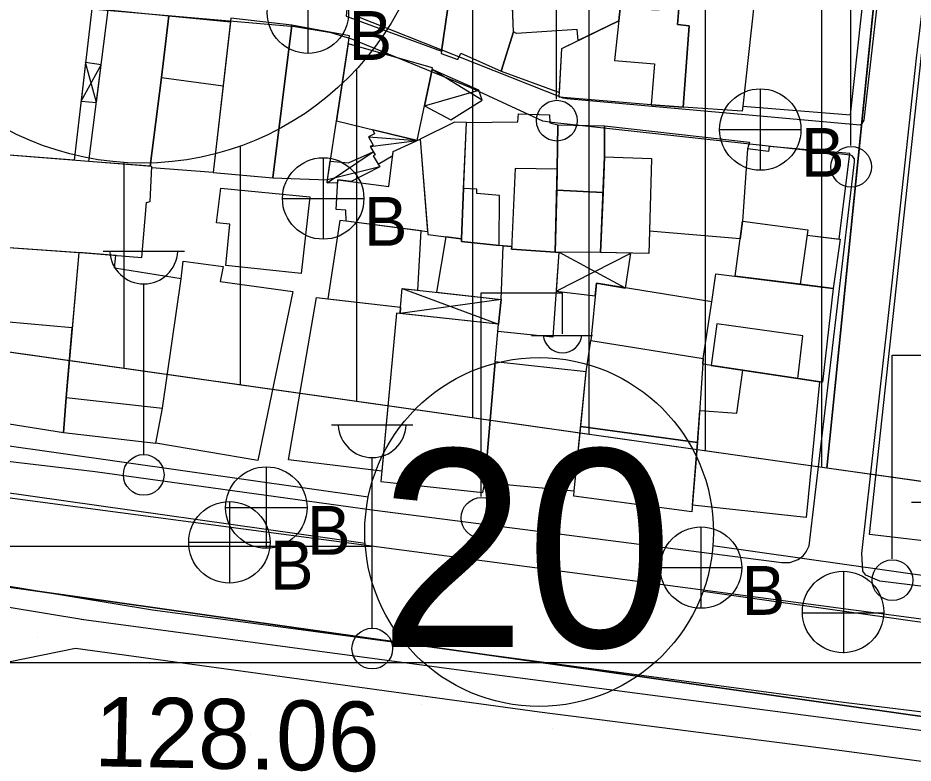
# Model space of a CAD drawing. Extents: x 417997 to 421451, y 4451742 to 4455216.
# Drawn here: x 419493.1 to 419570.1, y 4452369.2 to 4452433.3 of the extents above; entities that cross this region are included whole.
import ezdxf

# ---------------------------------------------------------------- set-up
doc = ezdxf.new("R2010")
doc.units = 0
for name, color, linetype in [('ADA', 7, 'Continuous'), ('ADAKENARI', 7, 'Continuous'), ('B_Mesken', 7, 'Continuous'), ('B_Sundurma', 7, 'Continuous'), ('B_Teras', 7, 'Continuous'), ('Default', 7, 'Continuous'), ('KALDIRIM', 7, 'Continuous'), ('KD_DAIRE', 7, 'Continuous'), ('KD_YGEN', 7, 'Continuous'), ('PL_AYA_REKREASYON_AL', 7, 'Continuous'), ('PL_KON_MEV_350', 7, 'Continuous'), ('PL_SAY_ORTAOGRETIM', 7, 'Continuous'), ('S_Cad_Sok_Lambasi', 7, 'Continuous'), ('S_Elektrik_Diregi', 7, 'Continuous'), ('S_Rogar_Kapagi', 7, 'Continuous'), ('S_Rogar_Kapagi_Buski', 7, 'Continuous'), ('Sinir_Duvar_tek_tarafa_ait', 7, 'Continuous'), ('SIT_TR_KULTUR', 7, 'Continuous'), ('SM_DAIRE', 7, 'Continuous'), ('SN_KULTUR_REKREASYON', 7, 'Continuous'), ('TR_ORTAYOGUNKONUT', 7, 'Continuous'), ('TR_PARKALANI', 7, 'Continuous'), ('Y_Kot_Noktasi', 7, 'Continuous'), ('Yol_Kaldirim_kenari_bordurtasi', 7, 'Continuous'), ('Yol_Sose', 7, 'Continuous')]:
    doc.layers.add(name, color=color, linetype=linetype)

# ---------------------------------------------------------------- blocks, each defined once
blk = doc.blocks.new('POINT_DISPLAY')
at = {"layer": 'Default'}
blk.add_line((0, 0), (0, 0), dxfattribs=at)

msp = doc.modelspace()

# ---------------------------------------------------------------- linework, layer by layer
at = {"layer": 'ADA'}
msp.add_line((419567.658, 4452443.954), (419562.661, 4452394.609), dxfattribs=at)
msp.add_line((419567.658, 4452443.954), (419562.661, 4452394.609), dxfattribs=at)
at = {"layer": 'ADAKENARI'}
for p, q in [((419562.661, 4452394.609), (419462.91, 4452408.734)), ((419562.661, 4452394.609), (419462.91, 4452408.734)), ((419687.358, 4452376.952), (419562.661, 4452394.609)), ((419687.358, 4452376.952), (419562.661, 4452394.609)), ((419457, 4452389.371), (419746.184, 4452348.423)), ((419457, 4452389.371), (419746.184, 4452348.423))]:
    msp.add_line(p, q, dxfattribs=at)
at = {"layer": 'B_Mesken'}
for points in [[(419534.636, 4452428.737), (419535.697, 4452432.128), (419535.439, 4452438.84), (419529.54, 4452438.143), (419530.016, 4452433.988), (419529.484, 4452430.246), (419530.911, 4452429.721), (419531.173, 4452430.279)], [(419535.451, 4452438.544), (419544.263, 4452439.061), (419544.501, 4452438.07), (419545.148, 4452434.142), (419544.882, 4452434.154), (419544.761, 4452433.049), (419541.274, 4452431.357), (419541.187, 4452432.317), (419535.955, 4452431.977), (419535.697, 4452432.128)], [(419529.578, 4452437.816), (419521.616, 4452437.017), (419521.304, 4452433.452), (419529.513, 4452430.454), (419530.016, 4452433.988)], [(419545.148, 4452434.142), (419544.501, 4452438.07), (419550.848, 4452437.805), (419550.868, 4452434.889), (419556.398, 4452434.611), (419555.425, 4452425.719), (419555.383, 4452425.28), (419550.308, 4452425.64), (419550.829, 4452432.619), (419549.824, 4452432.742), (419549.929, 4452434.129), (419548.261, 4452434.335), (419548.24, 4452434.006)], [(419556.657, 4452436.972), (419555.425, 4452425.719), (419564.699, 4452424.987), (419565.931, 4452436.2)], [(419490.461, 4452421.659), (419492.124, 4452434.775), (419499.427, 4452434.098), (419497.91, 4452421.073)], [(419499.179, 4452420.974), (419500.841, 4452433.998), (419506.07, 4452433.478), (419505.424, 4452428.194), (419504.46, 4452420.558)], [(419547.542, 4452425.83), (419539.643, 4452426.509), (419539.857, 4452430.67), (419544.761, 4452433.049), (419544.882, 4452434.154), (419548.24, 4452434.006), (419548.261, 4452434.335), (419549.929, 4452434.129), (419549.824, 4452432.742), (419550.829, 4452432.619), (419550.308, 4452425.64)], [(419509.876, 4452420.017), (419504.585, 4452420.427), (419504.591, 4452420.548), (419504.46, 4452420.558), (419505.424, 4452428.194), (419506.07, 4452433.478), (419511.362, 4452432.983)], [(419511.397, 4452433.288), (419509.876, 4452420.017), (419515.002, 4452419.559), (419516.642, 4452432.69)], [(419515.002, 4452419.559), (419519.695, 4452419.381), (419521.594, 4452431.767), (419516.642, 4452432.69)], [(419534.636, 4452428.737), (419539.663, 4452426.892), (419539.857, 4452430.67), (419541.274, 4452431.357), (419541.187, 4452432.317), (419535.955, 4452431.977), (419535.697, 4452432.128)], [(419520.472, 4452424.448), (419527.416, 4452422.772), (419528.727, 4452429.022), (419521.49, 4452431.088)], [(419539.289, 4452413.177), (419535.538, 4452413.441), (419535.548, 4452413.654), (419534.808, 4452413.72), (419534.473, 4452413.757), (419531.22, 4452414.089), (419531.231, 4452414.328), (419531.413, 4452418.641), (419531.653, 4452424.333), (419536.08, 4452424.366), (419536.122, 4452425.075), (419538.81, 4452424.974), (419538.818, 4452424.295), (419539.515, 4452424.119), (419539.463, 4452420.296), (419539.419, 4452418.514)], [(419527.688, 4452422.884), (419528.329, 4452414.678), (419531.231, 4452414.328), (419531.653, 4452424.333), (419530.626, 4452424.357)], [(419539.515, 4452424.119), (419543.54, 4452424.036), (419543.541, 4452421.375), (419543.411, 4452418.289), (419539.419, 4452418.514), (419539.463, 4452420.296)], [(419543.541, 4452421.375), (419543.54, 4452424.036), (419556.008, 4452422.623), (419555.846, 4452422.045), (419555.407, 4452415.829), (419555.206, 4452414.309), (419547.403, 4452414.966), (419547.357, 4452413.06), (419543.194, 4452413.137), (419543.411, 4452418.289)], [(419528.309, 4452414.932), (419521.323, 4452415.827), (419521.276, 4452416.775), (419520.438, 4452416.849), (419520.596, 4452419.392), (419524.977, 4452418.806), (419525.357, 4452421.817), (419527.688, 4452422.884)], [(419503.729, 4452412.715), (419504.142, 4452417.447), (419504.441, 4452417.525), (419504.591, 4452420.548), (419490.461, 4452421.659), (419489.818, 4452413.745), (419498.457, 4452413.143)], [(419563.709, 4452414.299), (419564.624, 4452421.643), (419557.702, 4452422.26), (419557.64, 4452421.821), (419555.846, 4452422.045), (419555.407, 4452415.829), (419561.03, 4452415.08), (419560.966, 4452414.619)], [(419510.149, 4452415.697), (419510.518, 4452418.668), (419518.192, 4452417.939), (419517.451, 4452411.339), (419510.947, 4452412.012), (419511.318, 4452415.582)], [(419539.419, 4452418.514), (419543.411, 4452418.289), (419543.194, 4452413.137), (419539.289, 4452413.177)], [(419527.461, 4452409.902), (419527.764, 4452415.002), (419521.323, 4452415.827), (419520.774, 4452415.89), (419519.729, 4452409.166), (419525.976, 4452408.435), (419526.131, 4452410.051)], [(419560.966, 4452414.619), (419563.801, 4452414.288), (419563.193, 4452410.052), (419560.376, 4452410.406), (419554.783, 4452411.108), (419555.407, 4452415.829), (419561.03, 4452415.08)], [(419497.739, 4452406.664), (419488.104, 4452407.54), (419488.629, 4452414.021), (419489.834, 4452413.945), (419489.818, 4452413.745), (419498.309, 4452413.154)], [(419529.889, 4452414.49), (419529.07, 4452409.722), (419534.633, 4452409.099), (419534.808, 4452413.72), (419534.473, 4452413.757), (419531.22, 4452414.089), (419531.231, 4452414.328)], [(419504.93, 4452396.763), (419505.523, 4452399.767), (419507.121, 4452410.889), (419501.385, 4452411.796), (419501.503, 4452412.896), (419498.309, 4452413.154), (419497.214, 4452400.67), (419496.996, 4452397.681)], [(419539.604, 4452413.173), (419539.1, 4452405.875), (419534.349, 4452406.339), (419534.402, 4452406.969), (419534.633, 4452409.099), (419534.808, 4452413.72), (419535.548, 4452413.654), (419535.538, 4452413.441), (419539.289, 4452413.177)], [(419507.121, 4452410.889), (419507.284, 4452412.398), (419510.726, 4452411.933), (419510.461, 4452410.639), (419516.736, 4452409.801), (419513.715, 4452395.248), (419504.93, 4452396.763), (419505.523, 4452399.767)], [(419552.772, 4452408.888), (419553.119, 4452411.317), (419563.193, 4452410.052), (419562.289, 4452401.998), (419551.989, 4452403.536), (419552.022, 4452404.036)], [(419542.349, 4452405.581), (419552.022, 4452404.036), (419552.772, 4452408.888), (419542.842, 4452410.493)], [(419524.378, 4452394.348), (419516.363, 4452395.315), (419518.757, 4452409.279), (419525.976, 4452408.435), (419525.954, 4452407.902), (419525.636, 4452407.938)], [(419534.133, 4452403.751), (419534.402, 4452406.969), (419525.636, 4452407.938), (419524.295, 4452393.459), (419533.061, 4452392.501), (419533.245, 4452393.372)], [(419488.104, 4452407.54), (419487.461, 4452399.181), (419496.996, 4452397.681), (419497.214, 4452400.67), (419497.739, 4452406.664)], [(419552.022, 4452404.036), (419551.534, 4452396.822), (419541.484, 4452398.19), (419541.964, 4452402.888), (419542.349, 4452405.581)], [(419534.133, 4452403.751), (419533.245, 4452393.372), (419540.918, 4452392.648), (419541.964, 4452402.888)], [(419562.039, 4452402.036), (419560.872, 4452390.374), (419551.104, 4452391.419), (419551.534, 4452396.822), (419551.719, 4452399.55), (419554.915, 4452399.338), (419555.431, 4452403.022), (419560.171, 4452402.314)], [(419541.484, 4452398.19), (419551.534, 4452396.822), (419551.058, 4452390.84), (419540.889, 4452392.208), (419540.918, 4452392.648)]]:
    msp.add_lwpolyline(points, close=True, dxfattribs=at)
at = {"layer": 'B_Sundurma'}
for p, q in [((419498.502, 4452426.155), (419500.238, 4452429.268)), ((419499.825, 4452426.035), (419498.89, 4452429.484)), ((419533.008, 4452426.237), (419528.696, 4452428.872)), ((419528.04, 4452425.746), (419532.711, 4452427.108)), ((419523.221, 4452423.076), (419527.417, 4452422.76)), ((419523.388, 4452422.246), (419527.416, 4452422.772)), ((419519.677, 4452419.141), (419523.646, 4452421.807)), ((419524.202, 4452420.494), (419519.695, 4452419.381)), ((419539.371, 4452409.81), (419545.802, 4452413.089)), ((419545.348, 4452410.088), (419539.604, 4452413.173)), ((419526.131, 4452410.051), (419534.402, 4452406.969)), ((419534.633, 4452409.099), (419525.954, 4452407.902))]:
    msp.add_line(p, q, dxfattribs=at)
for points in [[(419498.502, 4452426.155), (419499.825, 4452426.035), (419500.238, 4452429.268), (419498.89, 4452429.484)], [(419528.04, 4452425.746), (419530.319, 4452424.546), (419533.008, 4452426.237), (419532.711, 4452427.108), (419528.696, 4452428.872)], [(419523.593, 4452423.695), (419523.752, 4452423.354), (419523.221, 4452423.076), (419523.628, 4452422.375), (419523.388, 4452422.246), (419523.806, 4452421.535), (419523.635, 4452421.456), (419524.063, 4452420.744), (419525.316, 4452421.491), (419525.357, 4452421.817), (419527.417, 4452422.76), (419527.416, 4452422.772)], [(419524.063, 4452420.744), (419524.202, 4452420.494), (419521.73, 4452419.24), (419520.596, 4452419.392), (419520.578, 4452419.108), (419519.677, 4452419.141), (419519.695, 4452419.381), (419519.942, 4452420.993), (419521.514, 4452420.857), (419523.646, 4452421.807), (419523.806, 4452421.535), (419523.635, 4452421.456)], [(419539.371, 4452409.81), (419542.734, 4452409.42), (419542.842, 4452410.493), (419545.348, 4452410.088), (419545.802, 4452413.089), (419543.194, 4452413.137), (419539.604, 4452413.173)], [(419525.976, 4452408.435), (419526.131, 4452410.051), (419534.633, 4452409.099), (419534.402, 4452406.969), (419525.954, 4452407.902)]]:
    msp.add_lwpolyline(points, close=True, dxfattribs=at)
at = {"layer": 'B_Teras'}
for points in [[(419544.882, 4452434.154), (419544.389, 4452429.661), (419547.832, 4452429.369), (419547.542, 4452425.83), (419550.308, 4452425.64), (419550.829, 4452432.619), (419549.824, 4452432.742), (419549.929, 4452434.129), (419548.261, 4452434.335), (419548.24, 4452434.006)], [(419509.876, 4452420.017), (419504.585, 4452420.427), (419504.591, 4452420.548), (419504.46, 4452420.558), (419505.424, 4452428.194), (419510.732, 4452427.483)], [(419547.404, 4452415.005), (419547.357, 4452413.06), (419543.194, 4452413.137), (419543.541, 4452421.375), (419547.58, 4452421.214)], [(419535.86, 4452420.35), (419535.538, 4452413.441), (419539.289, 4452413.177), (419539.463, 4452420.296)], [(419531.231, 4452414.328), (419531.22, 4452414.089), (419534.473, 4452413.757), (419534.487, 4452418.055), (419532.551, 4452418.222), (419532.562, 4452418.581), (419531.413, 4452418.641)], [(419554.783, 4452411.108), (419555.407, 4452415.829), (419561.03, 4452415.08), (419560.376, 4452410.406)], [(419498.309, 4452413.154), (419497.214, 4452400.67), (419505.523, 4452399.767), (419507.121, 4452410.889), (419501.385, 4452411.796), (419501.503, 4452412.896)], [(419560.171, 4452402.314), (419560.592, 4452405.973), (419553.208, 4452407.007), (419552.7, 4452403.43)]]:
    msp.add_lwpolyline(points, close=True, dxfattribs=at)
at = {"layer": 'KALDIRIM'}
for p, q in [((419523.215, 4452392.115), (419460.546, 4452400.988)), ((419523.215, 4452392.115), (419460.546, 4452400.988)), ((419522.944, 4452388.113), (419459.364, 4452397.116)), ((419522.944, 4452388.113), (419459.364, 4452397.116)), ((419747.671, 4452360.332), (419552.863, 4452387.917)), ((419747.671, 4452360.332), (419552.863, 4452387.917)), ((419747.175, 4452356.362), (419552.012, 4452383.997)), ((419747.175, 4452356.362), (419552.012, 4452383.997))]:
    msp.add_line(p, q, dxfattribs=at)
at = {"layer": 'KD_DAIRE'}
msp.add_circle((419537.911, 4452389.112), 15, dxfattribs=at)
msp.add_circle((419537.911, 4452389.112), 15, dxfattribs=at)
at = {"layer": 'PL_AYA_REKREASYON_AL'}
msp.add_line((419746.184, 4452348.423), (419457, 4452389.371), dxfattribs=at)
msp.add_line((419746.184, 4452348.423), (419457, 4452389.371), dxfattribs=at)
at = {"layer": 'PL_KON_MEV_350'}
msp.add_lwpolyline([(419567.658, 4452443.954), (419562.661, 4452394.609), (419462.91, 4452408.734), (419316.34, 4452479.861)], dxfattribs=at)
at = {"layer": 'PL_SAY_ORTAOGRETIM'}
msp.add_lwpolyline([(419659.386, 4452433.765), (419690.951, 4452406.625), (419690.066, 4452398.955), (419687.358, 4452376.952), (419562.661, 4452394.609), (419567.658, 4452443.954), (419624.577, 4452438.19)], close=True, dxfattribs=at)
msp.add_lwpolyline([(419659.386, 4452433.765), (419690.951, 4452406.625), (419690.066, 4452398.955), (419687.358, 4452376.952), (419562.661, 4452394.609), (419567.658, 4452443.954), (419624.577, 4452438.19)], close=True, dxfattribs=at)
at = {"layer": 'S_Cad_Sok_Lambasi'}
for p, q in [((419500.397, 4452413.271), (419507.397, 4452413.271)), ((419503.897, 4452395.771), (419503.897, 4452410.446)), ((419520.056, 4452398.34), (419527.056, 4452398.34)), ((419523.556, 4452380.84), (419523.556, 4452395.515)), ((419569.952, 4452391.671), (419576.952, 4452391.671))]:
    msp.add_line(p, q, dxfattribs=at)
for centre in [(419503.897, 4452394.021), (419523.556, 4452379.09)]:
    msp.add_circle(centre, 1.75, dxfattribs=at)
for centre in [(419503.897, 4452413.375), (419523.556, 4452398.444)]:
    msp.add_arc(centre, 2.929, 183.298, 356.90719, dxfattribs=at)
at = {"layer": 'S_Elektrik_Diregi'}
for p, q in [((419539.398, 4452426.313), (419539.398, 4452443.813)), ((419564.718, 4452422.341), (419564.718, 4452439.841)), ((419532.917, 4452392.161), (419532.917, 4452409.661)), ((419532.917, 4452409.661), (419539.917, 4452409.661)), ((419539.917, 4452406.161), (419539.917, 4452409.661)), ((419537.257, 4452406.021), (419542.507, 4452406.021)), ((419568.263, 4452386.809), (419568.263, 4452404.309)), ((419568.263, 4452404.309), (419575.263, 4452404.309))]:
    msp.add_line(p, q, dxfattribs=at)
for centre in [(419539.434, 4452424.478), (419564.754, 4452420.506), (419532.953, 4452390.326), (419568.299, 4452384.973)]:
    msp.add_circle(centre, 1.75, dxfattribs=at)
msp.add_arc((419539.918, 4452406.174), 1.658, 184.83843, 355.14641, dxfattribs=at)
at = {"layer": 'S_Rogar_Kapagi'}
for p, q in [((419564.109, 4452378.709), (419564.109, 4452385.709)), ((419560.539, 4452382.174), (419567.539, 4452382.174))]:
    msp.add_line(p, q, dxfattribs=at)
msp.add_circle((419564.056, 4452382.238), 3.5, dxfattribs=at)
at = {"layer": 'S_Rogar_Kapagi_Buski'}
for p, q in [((419518.023, 4452437.265), (419518.023, 4452430.265)), ((419556.933, 4452427.215), (419556.933, 4452420.215)), ((419553.433, 4452423.715), (419560.433, 4452423.715)), ((419519.333, 4452421.286), (419519.333, 4452414.286)), ((419515.833, 4452417.786), (419522.833, 4452417.786)), ((419514.443, 4452394.716), (419514.443, 4452387.716)), ((419511.263, 4452391.726), (419511.263, 4452384.726)), ((419510.943, 4452391.216), (419517.943, 4452391.216)), ((419551.833, 4452389.556), (419551.833, 4452382.556)), ((419507.763, 4452388.226), (419514.763, 4452388.226)), ((419548.333, 4452386.056), (419555.333, 4452386.056))]:
    msp.add_line(p, q, dxfattribs=at)
for centre in [(419518.023, 4452433.765), (419556.933, 4452423.715), (419519.333, 4452417.786), (419514.443, 4452391.216), (419511.263, 4452388.226), (419551.833, 4452386.056)]:
    msp.add_circle(centre, 3.5, dxfattribs=at)
at = {"layer": 'Sinir_Duvar_tek_tarafa_ait'}
for points in [[(419611.72, 4452383.569), (419566.314, 4452388.908), (419572.274, 4452443.575), (419618.995, 4452438.277), (419660.716, 4452432.816), (419680.746, 4452415.705)], [(419448.361, 4452374.806), (419449.762, 4452375.579), (419450.624, 4452376.075), (419452.667, 4452377.445), (419468.665, 4452373.244), (419486.608, 4452376.806), (419498.029, 4452379.117), (419516.631, 4452376.563), (419537.931, 4452373.659), (419563.527, 4452370.397), (419589.022, 4452366.976), (419618.734, 4452363.038), (419642.331, 4452359.964), (419680.1, 4452354.952)]]:
    msp.add_lwpolyline(points, dxfattribs=at)
at = {"layer": 'SIT_TR_KULTUR'}
for p, q in [((419110.241, 4452387.891), (419523.484, 4452387.891)), ((419110.241, 4452387.891), (419523.484, 4452387.891)), ((419110.134, 4452377.891), (419599.001, 4452377.891)), ((419110.134, 4452377.891), (419599.001, 4452377.891))]:
    msp.add_line(p, q, dxfattribs=at)
at = {"layer": 'SM_DAIRE'}
msp.add_circle((419503.798, 4452445.833), 25, dxfattribs=at)
msp.add_circle((419503.798, 4452445.833), 25, dxfattribs=at)
at = {"layer": 'SN_KULTUR_REKREASYON'}
msp.add_line((419780.252, 4452353.89), (419451.753, 4452397.389), dxfattribs=at)
msp.add_line((419780.252, 4452353.89), (419451.753, 4452397.389), dxfattribs=at)
at = {"layer": 'TR_ORTAYOGUNKONUT'}
for p, q in [((419532.22, 4452398.919), (419532.22, 4452496.464)), ((419532.22, 4452398.919), (419532.22, 4452496.464)), ((419542.22, 4452397.503), (419542.22, 4452495.483)), ((419542.22, 4452397.503), (419542.22, 4452495.483)), ((419552.22, 4452396.087), (419552.22, 4452494.502)), ((419552.22, 4452396.087), (419552.22, 4452494.502)), ((419562.22, 4452394.671), (419562.22, 4452493.521)), ((419562.22, 4452394.671), (419562.22, 4452493.521)), ((419522.22, 4452400.335), (419522.22, 4452428.933)), ((419522.22, 4452400.335), (419522.22, 4452428.933)), ((419512.22, 4452401.751), (419512.22, 4452422.295)), ((419512.22, 4452401.751), (419512.22, 4452422.295)), ((419502.22, 4452403.167), (419502.22, 4452420.883)), ((419502.22, 4452403.167), (419502.22, 4452420.883))]:
    msp.add_line(p, q, dxfattribs=at)
at = {"layer": 'Yol_Kaldirim_kenari_bordurtasi'}
for points in [[(419444.875, 4452392.746), (419451.159, 4452390.757), (419469.008, 4452386.571), (419482.224, 4452384.314), (419498.752, 4452381.588)], [(419498.519, 4452381.62), (419531.652, 4452377.182), (419578.39, 4452371.068)]]:
    msp.add_lwpolyline(points, dxfattribs=at)
at = {"layer": 'Yol_Sose'}
for points in [[(419570.776, 4452467.72), (419565.837, 4452424.522), (419565.655, 4452424.222), (419565.514, 4452424.102), (419540.291, 4452426.344), (419539.99, 4452426.405), (419522.024, 4452433.508)], [(419680.254, 4452369.398), (419650.127, 4452373.883), (419602.133, 4452380.618), (419567.203, 4452384.9), (419566.023, 4452385.405), (419565.744, 4452385.746), (419565.669, 4452387.267), (419568.27, 4452410.533), (419570.379, 4452429.848), (419572.028, 4452443.659), (419572.15, 4452443.919), (419572.431, 4452444.198), (419572.832, 4452444.236), (419614.267, 4452439.286), (419634.483, 4452436.623), (419660.83, 4452433.255), (419661.551, 4452432.932), (419661.911, 4452432.71), (419680.756, 4452416.668)], [(419489.249, 4452395.561), (419499.73, 4452394.301), (419523.536, 4452391.005), (419558.786, 4452386.503), (419559.466, 4452386.501), (419560.188, 4452386.738), (419560.609, 4452387.056), (419560.89, 4452387.395), (419561.132, 4452387.914), (419565.045, 4452420.937), (419565.025, 4452421.197), (419564.846, 4452421.458), (419564.706, 4452421.499), (419538.998, 4452424.322), (419538.237, 4452424.445), (419532.043, 4452427.31), (419521.789, 4452431.471), (419520.03, 4452432.018), (419516.889, 4452432.531), (419500.023, 4452434.018)], [(419473.745, 4452376.738), (419491.54, 4452379.376), (419470.933, 4452382.923), (419447.673, 4452388.602), (419442.552, 4452390.061), (419442.297, 4452390.626), (419442.329, 4452390.892), (419445.929, 4452393.514), (419447.17, 4452394.209), (419448.684, 4452393.886), (419464.599, 4452389.151), (419479.539, 4452386.407), (419491.27, 4452384.632), (419504.647, 4452382.425), (419516.545, 4452380.851)], [(419516.545, 4452380.851), (419534.037, 4452378.503), (419564.096, 4452374.479), (419573.722, 4452373.299), (419574.702, 4452372.935), (419580.638, 4452369.929), (419581.479, 4452369.826), (419610.918, 4452365.884), (419618.03, 4452367.317), (419619.312, 4452367.372), (419658.957, 4452362.048), (419680.144, 4452359.116)]]:
    msp.add_lwpolyline(points, dxfattribs=at)

# ---------------------------------------------------------------- block references
at = {"layer": 'TR_PARKALANI', "xscale": 0.1, "yscale": 0.10000000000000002}
for p in [(419494.775, 4452380.026), (419494.775, 4452380.026), (419506.38, 4452380.68), (419506.38, 4452380.68), (419504.419, 4452377.773), (419504.419, 4452377.773), (419542.585, 4452376.91), (419542.585, 4452376.91), (419524.319, 4452374.817), (419524.319, 4452374.817), (419527.813, 4452374.305), (419527.813, 4452374.305), (419554.732, 4452374.531), (419554.732, 4452374.531), (419513.041, 4452371.7), (419513.041, 4452371.7), (419539.092, 4452372.212), (419539.092, 4452372.212), (419564.017, 4452370.534), (419564.017, 4452370.534)]:
    msp.add_blockref('POINT_DISPLAY', p, dxfattribs=at)

# ---------------------------------------------------------------- texts
at = {"layer": 'KD_YGEN'}
msp.add_text('20', height=17, dxfattribs=at).set_placement((419524.147, 4452379.216))
msp.add_text('20', height=17, dxfattribs=at).set_placement((419524.147, 4452379.216))
at = {"layer": 'S_Rogar_Kapagi_Buski'}
for p in [(419521.523, 4452429.701), (419560.433, 4452419.651), (419522.833, 4452413.722), (419517.943, 4452387.152), (419514.763, 4452384.162), (419555.333, 4452381.992)]:
    msp.add_text('B', height=4.2, dxfattribs=at).set_placement(p)
at = {"layer": 'Y_Kot_Noktasi'}
msp.add_text('128.06 ', height=6, rotation=358.87031, dxfattribs=at).set_placement((419499.606, 4452368.983))

doc.saveas('drawing.dxf')
